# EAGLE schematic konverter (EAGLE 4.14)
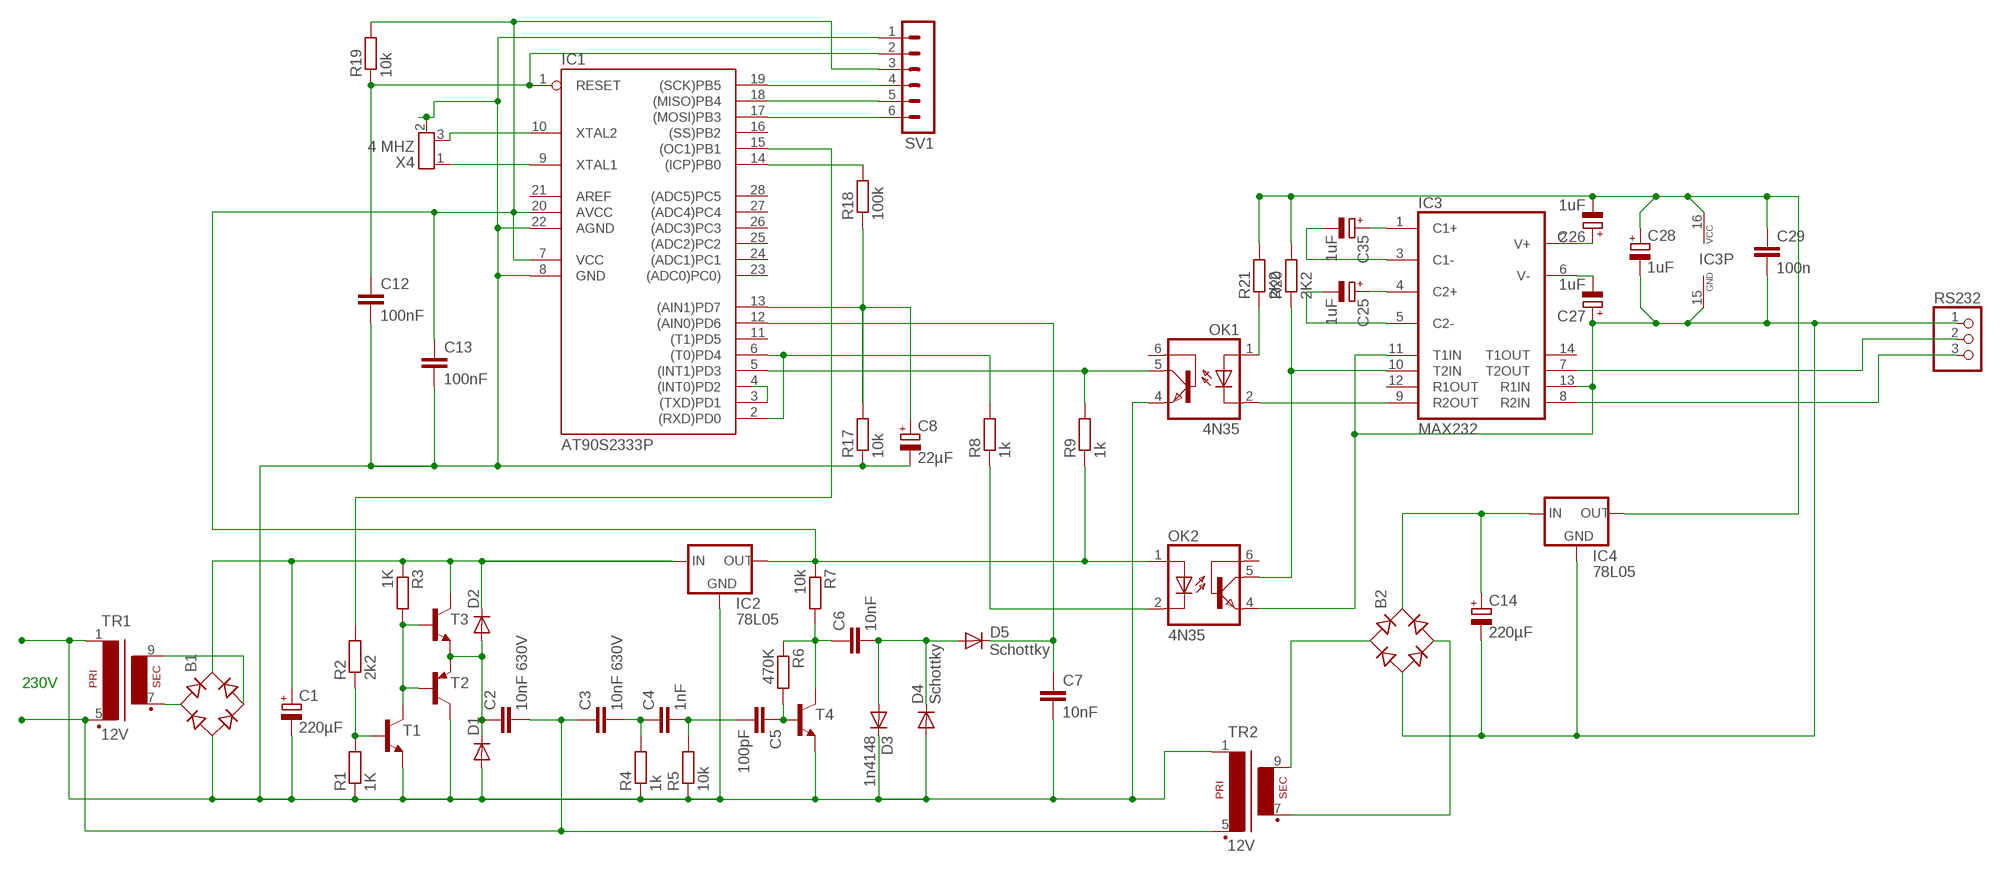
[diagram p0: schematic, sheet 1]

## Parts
B1  B-DIL  [B-DIL]
B2  B-DIL  [B-DIL]
C1  220µF  CPOL-EUE5-10.5  [E5-10,5]
C2  10nF 630V  C-EU102-043X133  [C102-043X133]
C3  10nF 630V  C-EU102-043X133  [C102-043X133]
C4  1nF  C-EU025-024X044  [C025-024X044]
C5  100pF  C-EU050-024X044  [C050-024X044]
C6  10nF  C-EU025-024X044  [C025-024X044]
C7  10nF  C-EU050-024X044  [C050-024X044]
C8  22µF  CPOL-EUE5-10.5  [E5-10,5]
C12  100nF  C-EU050-024X044  [C050-024X044]
C13  100nF  C-EU050-024X044  [C050-024X044]
C14  220µF  CPOL-EUE5-10.5  [E5-10,5]
C25  1uF  CPOL-EUE2.5-5  [E2,5-5]
C26  1uF  CPOL-EUE2.5-5  [E2,5-5]
C27  1uF  CPOL-EUE2.5-5  [E2,5-5]
C28  1uF  CPOL-EUE2.5-5  [E2,5-5]
C29  100n  C-EUC1206  [C1206]
C35  1uF  CPOL-EUE2.5-5  [E2,5-5]
D1  DIODE-D-5  [D-5]
D2  DIODE-D-2.5  [D-2.5]
D3  1n4148  DIODE-D-2.5  [D-2.5]
D4  Schottky  DIODE-D-2.5  [D-2.5]
D5  Schottky  DIODE-D-2.5  [D-2.5]
IC1  AT90S2333P  [DIL28-3]
IC2  78L05  78XXS  [78XXS]
IC3  MAX232  [DIL16]
IC4  78L05  78XXS  [78XXS]
OK1  4N35  [DIL06]
OK2  4N35  [DIL06]
R1  1K  R-EU_0207/5V  [0207/5V]
R2  2k2  R-EU_0207/5V  [0207/5V]
R3  1K  R-EU_0207/2V  [0207/2V]
R4  1k  R-EU_0207/5V  [0207/5V]
R5  10k  R-EU_0207/5V  [0207/5V]
R6  470K  R-EU_0207/2V  [0207/2V]
R7  10k  R-EU_0207/2V  [0207/2V]
R8  1k  R-EU_0207/5V  [0207/5V]
R9  1k  R-EU_0207/5V  [0207/5V]
R17  10k  R-EU_0207/2V  [0207/2V]
R18  100k  R-EU_0207/2V  [0207/2V]
R19  10k  R-EU_0207/2V  [0207/2V]
R20  2K2  R-EU_0207/2V  [0207/2V]
R21  2K2  R-EU_0207/2V  [0207/2V]
RS232  PINHD-1X3  [1X03]
SV1  MA06-1  [MA06-1]
T1  BC547A-NPN-TO92-EBC  [TO92-EBC]
T2  BC558A-PNP-TO92-EBC  [TO92-EBC]
T3  BC547A-NPN-TO92-EBC  [TO92-EBC]
T4  BC547A-NPN-TO92-EBC  [TO92-EBC]
TR1  12V  EI30-1  [EI30-1]
TR2  12V  EI30-1  [EI30-1]
X4  4 MHZ  RESONZTT  [RESONZTT]

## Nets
5V: C13.1 IC1.7(VCC) IC1.20(AVCC) IC2.OUT R7.1 R19.2 SV1.3
GND1: B1.- C1.- C7.2 C8.- C12.2 C13.2 D1.A D3.C D4.A IC1.8(GND) IC1.22(AGND) IC2.GND OK1.4(EMI) R1.1 R4.1 R5.1 R17.1 SV1.1 T1.E T2.C T4.E TR1.1 TR2.1 X4.2(GND)
GND3: B2.- C14.- C27.+ C28.- C29.2 IC3.11(T1IN) IC3.13(R1IN) IC3.15(GND) IC4.GND OK2.4(EMI) RS232.1
N$1: R1.2 R2.1 T1.B
N$2: C7.1 D5.C IC1.12((AIN0)PD6)
N$3: C6.1 R6.1 R7.2 T4.C
N$4: C6.2 D3.A D4.C D5.A
N$5: IC1.15((OC1)PB1) R2.2
N$6: C5.1 R6.2 T4.B
N$7: IC1.3((TXD)PD1) IC1.4((INT0)PD2)
N$8: IC1.5((INT1)PD3) OK1.5(COL) R9.2
N$10: IC1.17((MOSI)PB3) SV1.6
N$11: C12.1 IC1.1(RESET) R19.1 SV1.2
N$12: OK2.2(C) R8.1
N$13: C2.1 D1.C D2.A T2.E T3.E
N$14: B1.+ C1.+ D2.C IC2.IN R3.1 T3.C
N$15: R3.2 T1.C T2.B T3.B
N$16: IC1.18((MISO)PB4) SV1.5
N$17: IC1.19((SCK)PB5) SV1.4
N$19: B1.AC1 TR1.7
N$33: C4.2 C5.2 R5.2
N$34: IC1.2((RXD)PD0) IC1.6((T0)PD4) R8.2
N$35: C8.+ IC1.13((AIN1)PD7) R17.2 R18.1
N$36: IC1.14((ICP)PB0) R18.2
N$37: C3.2 C4.1 R4.2
N$38: B1.AC2 TR1.9
N$39: OK1.1(A) R21.1
N$40: OK2.1(A) R9.1
N$42: IC3.10(T2IN) OK2.5(COL) R20.1
N$43: C2.2 C3.1 TR1.5 TR2.5
N$44: B2.AC1 TR2.9
N$45: B2.AC2 TR2.7
N$46: B2.+ C14.+ IC4.IN
N$52: IC1.9(XTAL1) X4.1(X1)
N$53: IC1.10(XTAL2) X4.3(X2)
N$64: C25.+ IC3.4(C2+)
N$66: C35.+ IC3.1(C1+)
N$67: C25.- IC3.5(C2-)
N$68: C35.- IC3.3(C1-)
N$69: C27.- IC3.6(V-)
N$70: C26.+ IC3.2(V+)
N$73: IC3.8(R2IN) RS232.3
N$74: IC3.9(R2OUT) OK1.2(C)
N$77: IC3.7(T2OUT) RS232.2
VCCBATT: C26.- C28.+ C29.1 IC3.16(VCC) IC4.OUT R20.2 R21.2
Unconnected: IC1.11((T1)PD5) IC1.16((SS)PB2) IC1.23((ADC0)PC0)) IC1.24((ADC1)PC1) IC1.25((ADC2)PC2) IC1.26((ADC3)PC3) IC1.27((ADC4)PC4) IC1.28((ADC5)PC5) IC3.12(R1OUT) IC3.14(T1OUT) OK1.6(BAS) OK2.6(BAS)

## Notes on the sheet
- 230V

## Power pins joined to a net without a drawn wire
AREF: IC1.21(AREF)

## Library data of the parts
B1 B2 = rectifier:B-DIL: RECTIFIER
C1 C8 C14 C25-C28 C35 = rcl:CPOL-EU: POLARIZED CAPACITOR, European symbol
C2-C7 C12 C13 C29 = rcl:C-EU: CAPACITOR, European symbol
D1-D5 = diode:DIODE-: DIODE
IC1 = atmel:AT90S2333P: MICROCONTROLLER 2 Kbytes FLASH 128 bytes SRAM 128 bytes EEPROM UART 6-channel 10-bit ADC
IC2 IC4 = v-reg:78XXS: VOLTAGE REGULATOR
IC3 = maxim:MAX232: RS232 TRANSEIVER
OK1 OK2 = optocoupler:4N35: MOTOROLA OPTO COUPLER
R1-R9 R17-R21 = rcl:R-EU_: RESISTOR, European symbol
RS232 = pinhead:PINHD-1X3: PIN HEADER
SV1 = con-lstb:MA06-1: PIN HEADER
T1 T3 T4 = transistor:*-NPN-: NPN Transistror
T2 = transistor:*-PNP-: PNP Transistror
TR1 TR2 = trafo:EI30-1: TRANSFORMER 1 primary winding, 1 secondary winding ERA
X4 = ADS:RESONZTT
